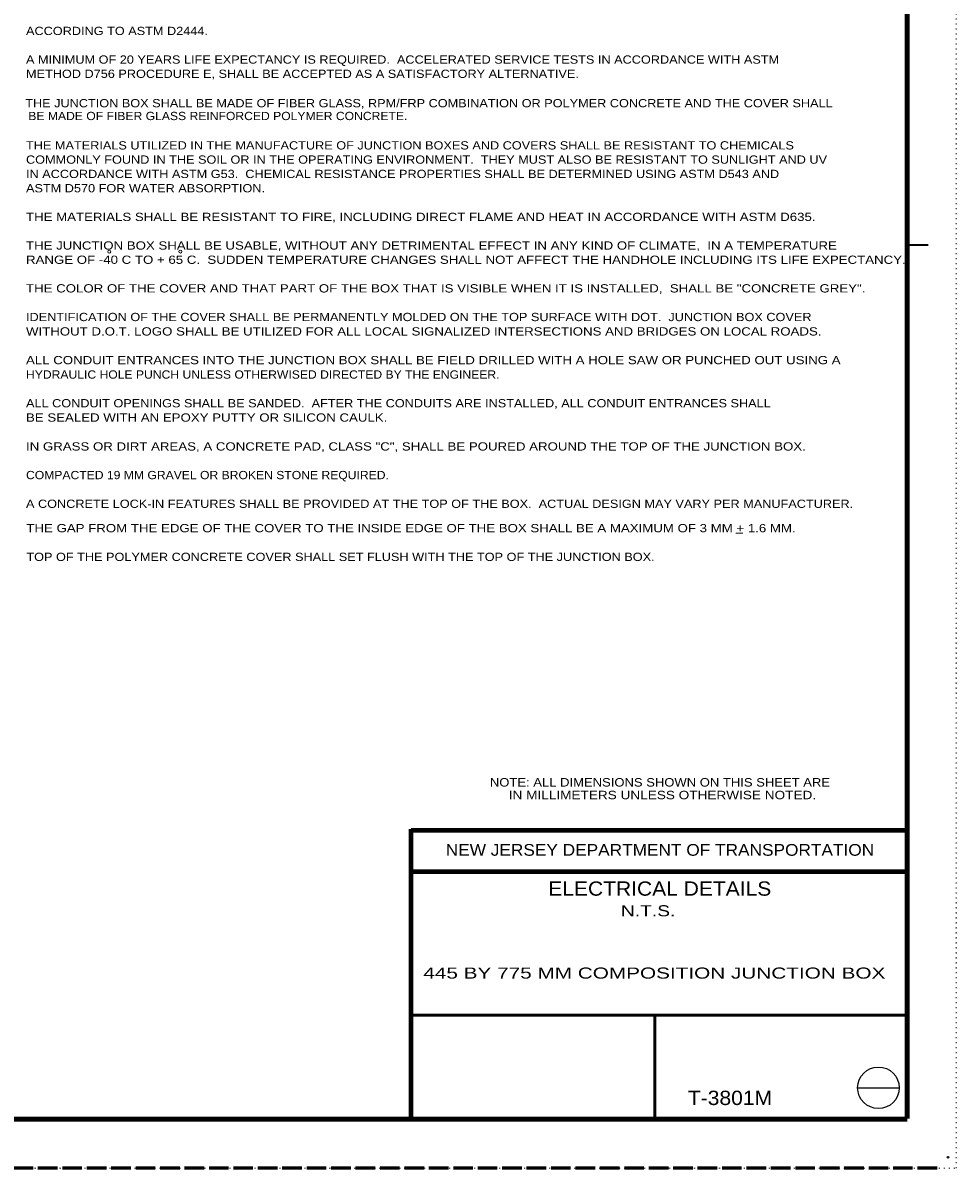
# Model space of a CAD drawing. Extents: x 312583 to 312854, y 144419 to 144597.
# Drawn here: x 312767.6 to 312853.5, y 144418.6 to 144524.1 of the extents above; entities that cross this region are included whole.
import ezdxf
from ezdxf.enums import TextEntityAlignment as Align

# ---------------------------------------------------------------- set-up
doc = ezdxf.new("R2010")
doc.units = 0
doc.header["$LTSCALE"] = 0.3
doc.header["$PDMODE"] = 32
doc.header["$PDSIZE"] = 0.15
doc.linetypes.add('DOTTED', pattern=[1.5, 0.3, -1.2])
doc.linetypes.add('LONG_DASHED', pattern=[7.5, 6, -1.5])
for name, color, linetype, lineweight in [('1', 7, 'Continuous', 25), ('10', 7, 'Continuous', 25), ('2', 7, 'Continuous', 13), ('39', 7, 'Continuous', 13), ('62', 7, 'DOTTED', 13), ('63', 7, 'LONG_DASHED', 60)]:
    doc.layers.add(name, color=color, linetype=linetype, lineweight=lineweight)

msp = doc.modelspace()

# ---------------------------------------------------------------- linework, layer by layer
at = {"layer": '1', "lineweight": 158}
for p, q in [((312849, 144423.1446), (312849, 144585.0846)), ((312616.5, 144423.0846), (312849, 144423.0846))]:
    msp.add_line(p, q, dxfattribs=at)
at = {"layer": '1', "lineweight": 35}
msp.add_line((312849, 144503.6216), (312850.932, 144503.6216), dxfattribs=at)
at = {"layer": '1', "lineweight": 80}
for p, q in [((312803.31, 144423.1446), (312803.31, 144449.8146)), ((312803.31, 144449.7246), (312849, 144449.7246)), ((312803.31, 144445.9146), (312849, 144445.9146))]:
    msp.add_line(p, q, dxfattribs=at)
at = {"layer": '1', "lineweight": 53}
for p, q in [((312849, 144432.6666), (312803.1073, 144432.6666)), ((312825.7546, 144432.6666), (312825.7546, 144423.1446))]:
    msp.add_line(p, q, dxfattribs=at)
at = {"layer": '1', "lineweight": 13}
for centre in [(312775.5094, 144502.9977), (312782.0625, 144503.0082)]:
    msp.add_circle(centre, 0.1414, dxfattribs=at)
at = {"layer": '1'}
msp.add_point((312852.75, 144419.5846), dxfattribs=at)
at = {"layer": '10'}
msp.add_line((312844.4383, 144425.9659), (312848.2793, 144425.9659), dxfattribs=at)
msp.add_circle((312846.3494, 144425.9805), 1.9159, dxfattribs=at)
at = {"layer": '39'}
msp.add_line((312833.225, 144477.081), (312833.8556, 144477.081), dxfattribs=at)
at = {"layer": '62'}
msp.add_lwpolyline([(312601.2, 144418.5846), (312853.5, 144418.5846), (312853.5, 144596.7846)], dxfattribs=at)
at = {"layer": '63'}
msp.add_line((312851.75, 144418.5846), (312583.526, 144418.5846), dxfattribs=at)

# ---------------------------------------------------------------- texts
at = {"layer": '1'}
for s, height, width, p in [('ACCORDING TO ASTM D2444.', 0.76, 1.15, (312767.8466, 144522.9511)), ('A MINIMUM OF 20 YEARS LIFE EXPECTANCY IS REQUIRED.  ACCELERATED SERVICE TESTS IN ACCORDANCE WITH ASTM', 0.76, 1.15, (312767.8466, 144520.3152)), ('METHOD D756 PROCEDURE E, SHALL BE ACCEPTED AS A SATISFACTORY ALTERNATIVE.', 0.76, 1.15, (312767.8466, 144519.0028)), ('THE JUNCTION BOX SHALL BE MADE OF FIBER GLASS, RPM/FRP COMBINATION OR POLYMER CONCRETE AND THE COVER SHALL', 0.76, 1.15, (312767.7766, 144516.2954)), ('BE MADE OF FIBER GLASS REINFORCED POLYMER CONCRETE.', 0.76, 1.1, (312768.0568, 144515.1169)), ('THE MATERIALS UTILIZED IN THE MANUFACTURE OF JUNCTION BOXES AND COVERS SHALL BE RESISTANT TO CHEMICALS', 0.76, 1.15, (312767.8466, 144512.4095)), ('COMMONLY FOUND IN THE SOIL OR IN THE OPERATING ENVIRONMENT.  THEY MUST ALSO BE RESISTANT TO SUNLIGHT AND UV', 0.76, 1.15, (312767.8466, 144511.0985)), ('IN ACCORDANCE WITH ASTM G53.  CHEMICAL RESISTANCE PROPERTIES SHALL BE DETERMINED USING ASTM D543 AND', 0.76, 1.15, (312767.8466, 144509.7798)), ('ASTM D570 FOR WATER ABSORPTION.', 0.76, 1.15, (312767.8466, 144508.4611)), ('THE MATERIALS SHALL BE RESISTANT TO FIRE, INCLUDING DIRECT FLAME AND HEAT IN ACCORDANCE WITH ASTM D635.', 0.76, 1.2, (312767.8466, 144505.8238)), ('THE JUNCTION BOX SHALL BE USABLE, WITHOUT ANY DETRIMENTAL EFFECT IN ANY KIND OF CLIMATE,  IN A TEMPERATURE', 0.76, 1.2, (312767.8466, 144503.1865)), ('RANGE OF -40 C TO + 65 C.  SUDDEN TEMPERATURE CHANGES SHALL NOT AFFECT THE HANDHOLE INCLUDING ITS LIFE EXPECTANCY.', 0.76, 1.2, (312767.8466, 144501.8755)), ('THE COLOR OF THE COVER AND THAT PART OF THE BOX THAT IS VISIBLE WHEN IT IS INSTALLED,  SHALL BE "CONCRETE GREY".', 0.76, 1.2, (312767.8466, 144499.2395)), ('IDENTIFICATION OF THE COVER SHALL BE PERMANENTLY MOLDED ON THE TOP SURFACE WITH DOT.  JUNCTION BOX COVER', 0.76, 1.15, (312767.8466, 144496.6008)), ('WITHOUT D.O.T. LOGO SHALL BE UTILIZED FOR ALL LOCAL SIGNALIZED INTERSECTIONS AND BRIDGES ON LOCAL ROADS.', 0.76, 1.2, (312767.8466, 144495.2745)), ('ALL CONDUIT ENTRANCES INTO THE JUNCTION BOX SHALL BE FIELD DRILLED WITH A HOLE SAW OR PUNCHED OUT USING A', 0.76, 1.2, (312767.8466, 144492.6295)), ('HYDRAULIC HOLE PUNCH UNLESS OTHERWISED DIRECTED BY THE ENGINEER.', 0.76, 1.1, (312767.8466, 144491.3031)), ('ALL CONDUIT OPENINGS SHALL BE SANDED.  AFTER THE CONDUITS ARE INSTALLED, ALL CONDUIT ENTRANCES SHALL', 0.76, 1.15, (312767.8466, 144488.6581)), ('BE SEALED WITH AN EPOXY PUTTY OR SILICON CAULK.', 0.76, 1.2, (312767.8466, 144487.3395)), ('IN GRASS OR DIRT AREAS, A CONCRETE PAD, CLASS "C", SHALL BE POURED AROUND THE TOP OF THE JUNCTION BOX.', 0.76, 1.2, (312767.8466, 144484.6791)), ('COMPACTED 19 MM GRAVEL OR BROKEN STONE REQUIRED.', 0.76, 1.1, (312767.8466, 144482.0418)), ('A CONCRETE LOCK-IN FEATURES SHALL BE PROVIDED AT THE TOP OF THE BOX.  ACTUAL DESIGN MAY VARY PER MANUFACTURER.', 0.76, 1.15, (312767.8466, 144479.3968)), ('THE GAP FROM THE EDGE OF THE COVER TO THE INSIDE EDGE OF THE BOX SHALL BE A MAXIMUM OF 3 MM + 1.6 MM.', 0.76, 1.2, (312767.8815, 144477.1515)), ('TOP OF THE POLYMER CONCRETE COVER SHALL SET FLUSH WITH THE TOP OF THE JUNCTION BOX.', 0.76, 1.15, (312767.8815, 144474.5065)), ('NOTE: ALL DIMENSIONS SHOWN ON THIS SHEET ARE', 0.78, 1.15, (312810.5657, 144453.7286)), ('     IN MILLIMETERS UNLESS OTHERWISE NOTED.', 0.78, 1.2, (312810.5656, 144452.5586))]:
    msp.add_text(s, height=height, dxfattribs=dict(at, width=width)).set_placement(p)
at = {"layer": '1', "width": 1.1}
for s, height, p in [('NEW JERSEY DEPARTMENT OF TRANSPORTATION', 1.08, (312826.2285, 144447.3546)), ('ELECTRICAL DETAILS', 1.315, (312826.2107, 144443.6759)), ('T-3801M', 1.319, (312832.6765, 144424.3942))]:
    msp.add_text(s, height=height, dxfattribs=at).set_placement(p, align=Align.CENTER)
at = {"layer": '2'}
for s, width, p in [('    N.T.S.  ', 1.3, (312824.6461, 144441.778)), ('        445 BY 775 MM COMPOSITION JUNCTION BOX          ', 1.4, (312826.2423, 144436.0399))]:
    msp.add_text(s, height=1.02, dxfattribs=dict(at, width=width)).set_placement(p, align=Align.CENTER)

doc.saveas('drawing.dxf')
